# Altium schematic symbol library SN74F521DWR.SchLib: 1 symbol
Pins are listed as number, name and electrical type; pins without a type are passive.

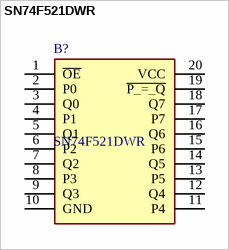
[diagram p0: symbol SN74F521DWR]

## SN74F521DWR
designator B?
8-Bit Identity/Magnitude Comparators (P=Q) with Enable; Manufacturer_Name: Texas Instruments; Geometry.Height: 2.65mm
footprint SOIC127P1030X265-20N
pins: 1 ~{OE}, 2 P0, 3 Q0, 4 P1, 5 Q1, 6 P2, 7 Q2, 8 P3, 9 Q3, 10 GND, 11 P4, 12 Q4, 13 P5, 14 Q5, 15 P6, 16 Q6, 17 P7, 18 Q7, 19 ~{P_=_Q}, 20 VCC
